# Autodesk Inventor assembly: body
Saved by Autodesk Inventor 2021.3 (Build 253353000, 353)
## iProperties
Created: 2022-07
Part Number: body
Document SubType Name: Assembly
Designer: Administrator
Title: body
Author: Administrator
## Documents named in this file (4)
- c:\worker\convert-fusion-r04\tmp\job-1\186\output\files\05ef811f-4573-476e-8ba5-de3f58aa0f0a\body.iam
- c:\worker\convert-fusion-r04\tmp\job-1\186\output\files\05ef811f-4573-476e-8ba5-de3f58aa0f0a\Thread insert, 3.2mm OD 3mm len.ipt
- c:\worker\convert-fusion-r04\tmp\job-1\186\output\files\05ef811f-4573-476e-8ba5-de3f58aa0f0a\Grub screw M2 3mm.ipt
- c:\worker\convert-fusion-r04\tmp\job-1\186\output\files\05ef811f-4573-476e-8ba5-de3f58aa0f0a\Part6.ipt
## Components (3 placed, 3 different names)
1. Thread insert, 3.2mm OD 3mm len:1
2. Grub screw M2 3mm:1
3. Part6
